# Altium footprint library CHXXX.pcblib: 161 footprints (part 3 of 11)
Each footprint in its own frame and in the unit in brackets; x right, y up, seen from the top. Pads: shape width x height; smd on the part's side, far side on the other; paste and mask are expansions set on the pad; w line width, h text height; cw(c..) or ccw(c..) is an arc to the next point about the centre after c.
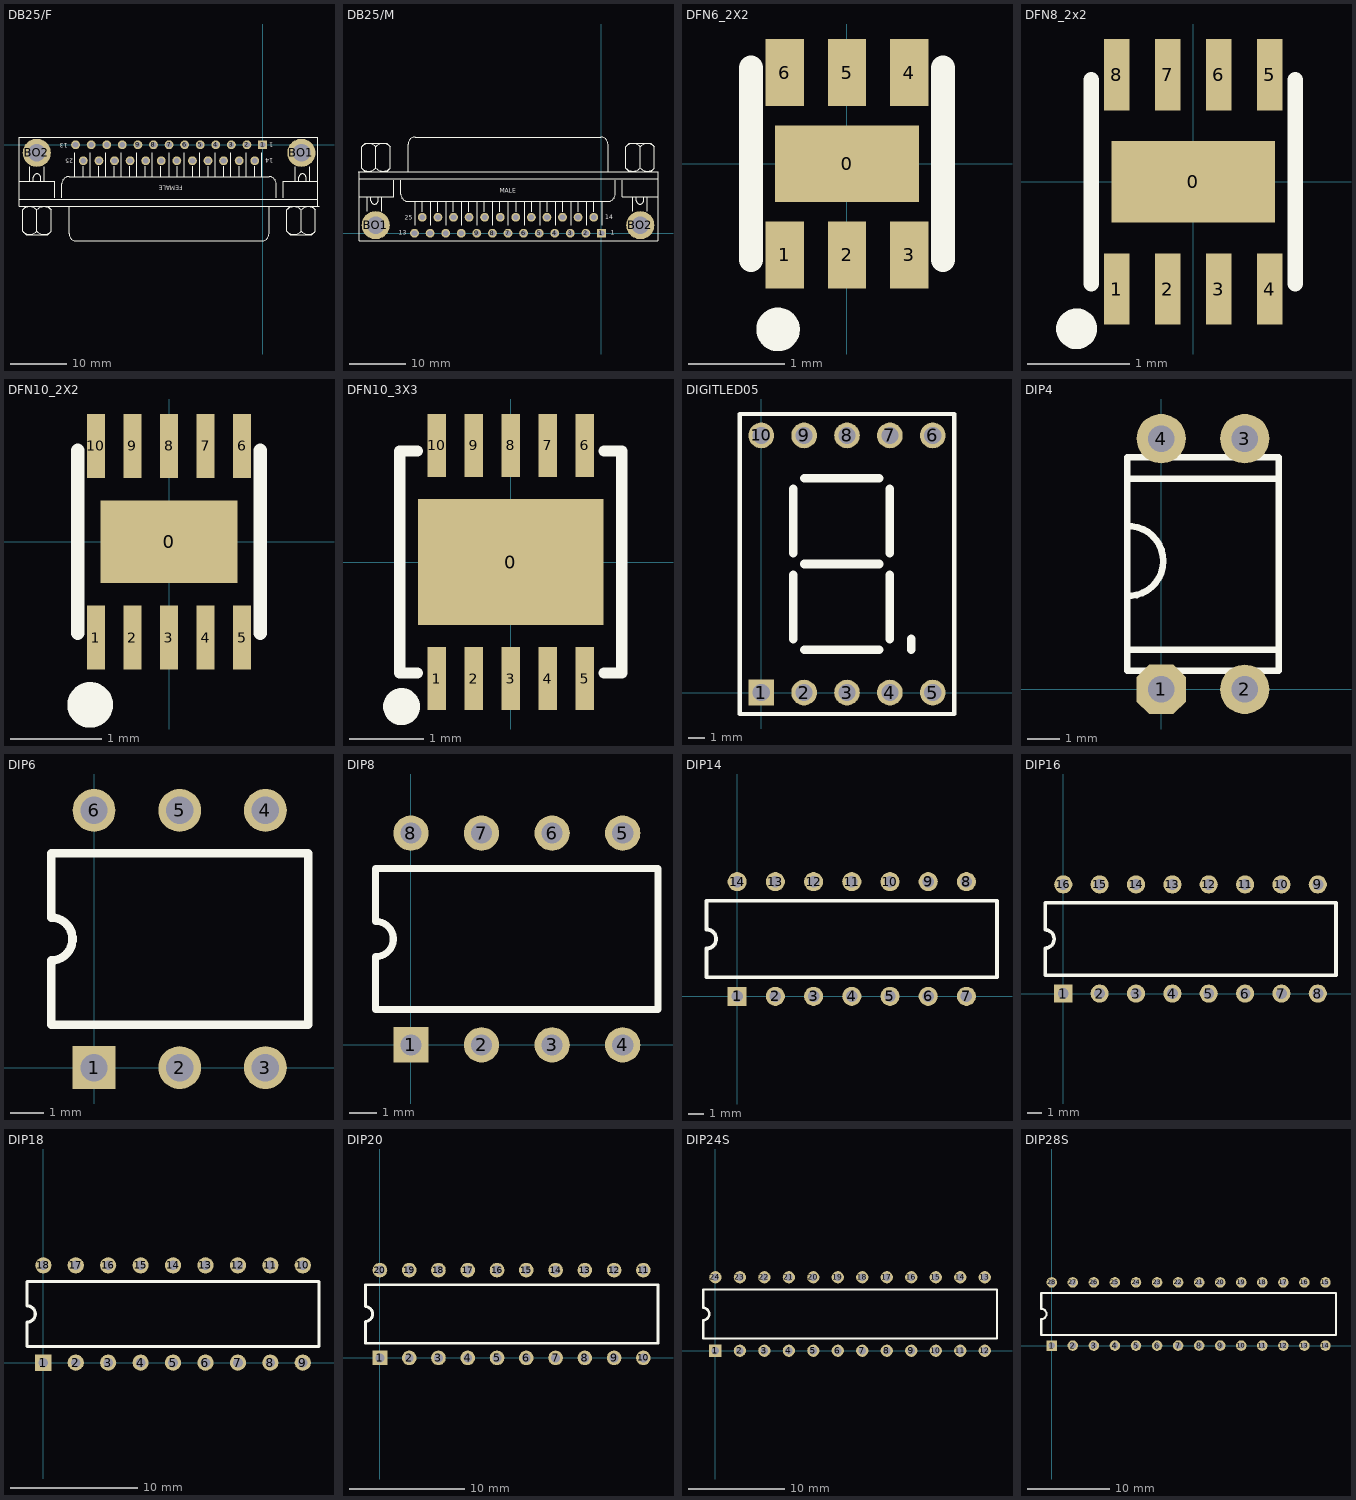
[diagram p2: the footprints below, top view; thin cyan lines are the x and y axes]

## DB25/F [mm]
pads (27):
  rect 1.575x1.575 hole 1.016: 1(0,0)
  round 1.575 hole 1.016: 2(-2.77,0) 3(-5.54,0) 4(-8.31,0) 5(-11.08,0) 6(-13.85,0) 7(-16.62,0) 8(-19.39,0) 9(-22.16,0) 10(-24.93,0) 11(-27.7,0) 12(-30.47,0) 13(-33.24,0) 14(-1.385,-2.84) 15(-4.155,-2.84) 16(-6.925,-2.84) 17(-9.695,-2.84) 18(-12.465,-2.84) 19(-15.235,-2.84) 20(-18.005,-2.84) 21(-20.775,-2.84) 22(-23.545,-2.84) 23(-26.315,-2.84) 24(-29.085,-2.84) 25(-31.855,-2.84)
  round 4.995 hole 3.18: BO1(6.9,-1.42) BO2(-40.14,-1.42)
TopOverlay:
  lines w0.203: -43.297,-6.436 -36.947,-6.436 -36.947,-9.455 ; -43.297,1.364 -43.297,-10.936 10.043,-10.936 ; -43.262,-9.636 9.838,-9.636 ; -43.262,1.364 9.838,1.364 9.838,-10.936 ; -42.665,-15.384 ccw(c-41.392,-14.111) -40.12,-15.384 ; -42.665,-11.569 cw(c-41.392,-12.841) -40.12,-11.569 ; -42.027,-10.936 -42.662,-11.571 -42.662,-15.381 -42.027,-16.016 -38.217,-16.016 -37.582,-15.381 -37.582,-11.571 -38.217,-10.936 ; -41.37,-6.436 -41.37,-3.896 ; -40.735,-6.436 -40.735,-5.801 cw(c-40.1,-5.801) -39.465,-5.801 -39.465,-6.436 ; -40.125,-15.384 ccw(c-38.852,-14.111) -37.58,-15.384 ; -40.125,-11.569 cw(c-38.852,-12.841) -37.58,-11.569 ; -40.122,-15.381 -40.122,-11.571 ; -38.83,-6.436 -38.83,-3.896 ; -35.677,-9.455 -35.677,-6.915 cw(c-34.407,-6.915) -34.407,-5.645 1.153,-5.645 cw(c1.153,-6.915) 2.423,-6.915 2.423,-9.455 ; -34.407,-10.936 -34.407,-15.805 ccw(c-33.137,-15.805) -33.137,-17.075 -32.502,-17.075 -0.117,-17.075 ccw(c-0.117,-15.805) 1.153,-15.805 1.153,-10.936 ; -33.349,-5.645 -33.349,-1.418 ; -31.867,-5.645 -31.867,-3.836 ; -30.597,-5.645 -30.597,-1.418 ; -29.116,-5.645 -29.116,-3.836 ; -27.846,-5.645 -27.846,-1.418 ; -26.364,-5.645 -26.364,-3.836 ; -25.094,-5.645 -25.094,-1.418 ; -23.612,-5.645 -23.612,-3.836 ; -22.342,-5.645 -22.342,-1.418 ; -20.861,-5.645 -20.861,-3.836 ; -19.591,-5.645 -19.591,-1.418 ; -18.109,-5.645 -18.109,-3.836 ; -16.627,-5.645 -16.627,-1.418 ; -15.146,-5.645 -15.146,-3.836 ; -13.876,-5.645 -13.876,-1.418 ; -12.394,-5.645 -12.394,-3.836 ; -11.124,-5.645 -11.124,-1.418 ; -9.642,-5.645 -9.642,-3.836 ; -8.372,-5.645 -8.372,-1.418 ; -6.891,-5.645 -6.891,-3.836 ; -5.621,-5.645 -5.621,-1.418 ; -4.139,-5.645 -4.139,-3.836 ; -2.869,-5.645 -2.869,-1.418 ; -1.387,-5.645 -1.387,-3.836 ; -0.117,-5.645 -0.117,-1.418 ; 3.693,-9.455 3.693,-6.436 9.838,-6.436 ; 4.325,-15.384 ccw(c5.598,-14.111) 6.87,-15.384 ; 4.325,-11.569 cw(c5.598,-12.841) 6.87,-11.569 ; 4.963,-10.936 4.328,-11.571 4.328,-15.381 4.963,-16.016 8.773,-16.016 9.408,-15.381 9.408,-11.571 8.773,-10.936 ; 5.83,-6.436 5.83,-3.896 ; 6.465,-6.436 6.465,-5.801 cw(c7.1,-5.801) 7.735,-5.801 7.735,-6.436 ; 6.865,-15.384 ccw(c8.138,-14.111) 9.41,-15.384 ; 6.865,-11.569 cw(c8.138,-12.841) 9.41,-11.569 ; 6.868,-15.381 6.868,-11.571 ; 8.37,-6.436 8.37,-3.896
  text "25" at -33.665,-2.445 h0.76
  text "13" at -34.59,0.283 h0.76
  text "1" at 1.865,0.395 h0.76
  text "14" at 1.87,-2.382 h0.76
  text "FEMALE" at -14.19,-7.256 h0.76

## DB25/M [mm]
pads (27):
  rect 1.575x1.575 hole 1.016: 1(0,0)
  round 1.575 hole 1.016: 2(-2.77,0) 3(-5.54,0) 4(-8.31,0) 5(-11.08,0) 6(-13.85,0) 7(-16.62,0) 8(-19.39,0) 9(-22.16,0) 10(-24.93,0) 11(-27.7,0) 12(-30.47,0) 13(-33.24,0) 14(-1.385,2.84) 15(-4.155,2.84) 16(-6.925,2.84) 17(-9.695,2.84) 18(-12.465,2.84) 19(-15.235,2.84) 20(-18.005,2.84) 21(-20.775,2.84) 22(-23.545,2.84) 23(-26.315,2.84) 24(-29.085,2.84) 25(-31.855,2.84)
  round 4.995 hole 3.18: BO1(-40.14,1.42) BO2(6.9,1.42)
TopOverlay:
  lines w0.203: -43.29,10.936 10.05,10.936 10.05,-1.364 ; -43.085,6.436 -36.94,6.436 -36.94,9.455 ; -43.085,9.636 10.015,9.636 ; -43.085,10.936 -43.085,-1.364 10.015,-1.364 ; -42.657,11.569 ccw(c-41.385,12.841) -40.113,11.569 ; -42.657,15.384 cw(c-41.385,14.111) -40.113,15.384 ; -42.02,10.936 -42.655,11.571 -42.655,15.381 -42.02,16.016 -38.21,16.016 -37.575,15.381 -37.575,11.571 -38.21,10.936 ; -41.618,3.896 -41.618,6.436 ; -40.983,6.436 -40.983,5.801 ccw(c-40.348,5.801) -39.713,5.801 -39.713,6.436 ; -40.117,11.569 ccw(c-38.845,12.841) -37.573,11.569 ; -40.117,15.384 cw(c-38.845,14.111) -37.573,15.384 ; -40.115,11.571 -40.115,15.381 ; -39.078,3.896 -39.078,6.436 ; -35.67,9.455 -35.67,6.915 ccw(c-34.4,6.915) -34.4,5.645 1.16,5.645 ccw(c1.16,6.915) 2.43,6.915 2.43,9.455 ; -34.4,10.936 -34.4,15.805 cw(c-33.13,15.805) -33.13,17.075 -0.745,17.075 -0.11,17.075 cw(c-0.11,15.805) 1.16,15.805 1.16,10.936 ; -33.13,1.418 -33.13,5.645 ; -31.86,3.836 -31.86,5.645 ; -30.378,1.418 -30.378,5.645 ; -29.108,3.836 -29.108,5.645 ; -27.627,1.418 -27.627,5.645 ; -26.357,3.836 -26.357,5.645 ; -24.875,1.418 -24.875,5.645 ; -23.605,3.836 -23.605,5.645 ; -22.123,1.418 -22.123,5.645 ; -20.853,3.836 -20.853,5.645 ; -19.372,1.418 -19.372,5.645 ; -18.102,3.836 -18.102,5.645 ; -16.62,1.418 -16.62,5.645 ; -15.138,3.836 -15.138,5.645 ; -13.657,1.418 -13.657,5.645 ; -12.387,3.836 -12.387,5.645 ; -10.905,1.418 -10.905,5.645 ; -9.635,3.836 -9.635,5.645 ; -8.153,1.418 -8.153,5.645 ; -6.883,3.836 -6.883,5.645 ; -5.402,1.418 -5.402,5.645 ; -4.132,3.836 -4.132,5.645 ; -2.65,1.418 -2.65,5.645 ; -1.38,3.836 -1.38,5.645 ; 0.102,1.418 0.102,5.645 ; 3.7,9.455 3.7,6.436 10.05,6.436 ; 4.333,11.569 ccw(c5.605,12.841) 6.877,11.569 ; 4.333,15.384 cw(c5.605,14.111) 6.877,15.384 ; 4.97,10.936 4.335,11.571 4.335,15.381 4.97,16.016 8.78,16.016 9.415,15.381 9.415,11.571 8.78,10.936 ; 5.582,3.896 5.582,6.436 ; 6.217,6.436 6.217,5.801 ccw(c6.852,5.801) 7.487,5.801 7.487,6.436 ; 6.873,11.569 ccw(c8.145,12.841) 9.417,11.569 ; 6.873,15.384 cw(c8.145,14.111) 9.417,15.384 ; 6.875,11.571 6.875,15.381 ; 8.122,3.896 8.122,6.436
  text "MALE" at -18.107,7.215 h0.76
  text "14" at 0.652,2.434 h0.76
  text "1" at 1.625,-0.317 h0.76
  text "13" at -36.002,-0.284 h0.76
  text "25" at -34.937,2.391 h0.76

## DFN6_2X2 [mm]
pads (7):
  rect 1.5x0.8 smd mask+0.051: 0(0,0)
  rect 0.4x0.7 smd mask+0.051: 1(-0.65,-0.95) 2(0,-0.95) 3(0.65,-0.95) 4(0.65,0.95) 5(0,0.95) 6(-0.65,0.95)
TopOverlay:
  circle w0.254: c-0.718,-1.725 r0.1
  lines w0.254: -1,-1 -1,1 ; 1,-1 1,1

## DFN8_2x2 [mm]
pads (9):
  rect 1.6x0.8 smd mask+0.05: 0(0,0)
  rect 0.25x0.7 smd mask+0.05: 1(-0.75,-1.05) 2(-0.25,-1.05) 3(0.25,-1.05) 4(0.75,-1.05) 5(0.75,1.05) 6(0.25,1.05) 7(-0.25,1.05) 8(-0.75,1.05)
TopOverlay:
  circle w0.2: c-1.144,-1.44 r0.1
  lines w0.152: -1,-1 -1,1 ; 1,-1 1,1

## DFN10_2X2 [mm]
pads (11):
  rect 1.5x0.9 smd mask+0.051: 0(0,0)
  rect 0.2x0.7 smd mask+0.051: 1(-0.8,-1.05) 2(-0.4,-1.05) 3(0,-1.05) 4(0.4,-1.05) 5(0.8,-1.05) 6(0.8,1.05) 7(0.4,1.05) 8(0,1.05) 9(-0.4,1.05) 10(-0.8,1.05)
TopOverlay:
  circle w0.3: c-0.864,-1.786 r0.1
  lines w0.152: -1,-1 -1,1 ; 1,-1 1,1

## DFN10_3X3 [mm]
pads (11):
  rect 2.5x1.7 smd mask+0.051: 0(0,0)
  rect 0.25x0.85 smd mask+0.051: 1(-1,-1.575) 2(-0.5,-1.575) 3(0,-1.575) 4(0.5,-1.575) 5(1,-1.575) 6(1,1.575) 7(0.5,1.575) 8(0,1.575) 9(-0.5,1.575) 10(-1,1.575)
TopOverlay:
  circle w0.3: c-1.474,-1.954 r0.1
  lines w0.152: -1.264,-1.5 -1.5,-1.5 -1.5,1.5 -1.264,1.5 ; 1.264,-1.5 1.5,-1.5 1.5,1.5 1.264,1.5

## DIGITLED05 [mil]
pads (10):
  rect 60x60 hole 40: 1(0,0)
  round 60 hole 40: 2(100,0) 3(200,0) 4(300,0) 5(400,0) 6(400,600) 7(300,600) 8(200,600) 9(100,600) 10(0,600)
TopOverlay:
  lines w10: -50,-50 450,-50 450,650 -50,650 -50,-50
  lines w20: 75,125 75,275 ; 75,325 75,475 ; 100,100 275,100 ; 100,300 275,300 ; 100,500 275,500 ; 300,125 300,275 ; 300,325 300,475 ; 350,100 350,125

## DIP4 [mm]
pads (4):
  oct 1.5x1.5 hole 0.8: 1(0,0)
  round 1.5 hole 0.8: 2(2.54,0) 3(2.54,7.62) 4(0,7.62)
TopOverlay:
  lines w0.2: -1,1.2 3.5,1.2 ; -1,6.4 3.57,6.4 ; -1.03,0.56 -1.03,7.06 3.57,7.06 3.57,0.56 -1.03,0.56
  lines w0.203: -0.912,2.841 ccw(c-1,3.9) -0.904,4.959

## DIP6 [mil]
pads (6):
  rect 50x50 hole 32: 1(0,0)
  round 50 hole 32: 2(100,0) 3(200,0) 4(200,300) 5(100,300) 6(0,300)
TopOverlay:
  lines w10: -50,50 250,50 250,250 -50,250 -50,175 cw(c-50,150) -50,125 -50,50

## DIP8 [mil]
pads (8):
  rect 50x50 hole 30: 1(0,0)
  round 50 hole 30: 2(100,0) 3(200,0) 4(300,0) 5(300,300) 6(200,300) 7(100,300) 8(0,300)
TopOverlay:
  lines w10: -50,50 -50,125 ccw(c-50,150) -50,175 -50,250 350,250 350,50 -50,50

## DIP14 [mil]
pads (14):
  rect 50x50 hole 30: 1(0,0)
  round 50 hole 30: 2(100,0) 3(200,0) 4(300,0) 5(400,0) 6(500,0) 7(600,0) 8(600,300) 9(500,300) 10(400,300) 11(300,300) 12(200,300) 13(100,300) 14(0,300)
TopOverlay:
  lines w10: -80,50 680,50 680,250 -80,250 -80,175 cw(c-80,150) -80,125 -80,50

## DIP16 [mil]
pads (16):
  rect 50x50 hole 30: 1(0,0)
  round 50 hole 30: 2(100,0) 3(200,0) 4(300,0) 5(400,0) 6(500,0) 7(600,0) 8(700,0) 9(700,300) 10(600,300) 11(500,300) 12(400,300) 13(300,300) 14(200,300) 15(100,300) 16(0,300)
TopOverlay:
  lines w10: -50,50 -50,125 ccw(c-50,150) -50,175 -50,250 750,250 750,50 -50,50

## DIP18 [mil]
pads (18):
  rect 50x50 hole 30: 1(0,0)
  round 50 hole 30: 2(100,0) 3(200,0) 4(300,0) 5(400,0) 6(500,0) 7(600,0) 8(700,0) 9(800,0) 10(800,300) 11(700,300) 12(600,300) 13(500,300) 14(400,300) 15(300,300) 16(200,300) 17(100,300) 18(0,300)
TopOverlay:
  lines w10: -50,50 850,50 850,250 -50,250 -50,175 cw(c-50,150) -50,125 -50,50

## DIP20 [mil]
pads (20):
  rect 50x50 hole 30: 1(0,0)
  round 50 hole 30: 2(100,0) 3(200,0) 4(300,0) 5(400,0) 6(500,0) 7(600,0) 8(700,0) 9(800,0) 10(900,0) 11(900,300) 12(800,300) 13(700,300) 14(600,300) 15(500,300) 16(400,300) 17(300,300) 18(200,300) 19(100,300) 20(0,300)
TopOverlay:
  lines w10: -50,50 950,50 950,250 -50,250 -50,175 cw(c-50,150) -50,125 -50,50

## DIP24S [mil]
pads (24):
  rect 50x50 hole 30: 1(0,0)
  round 50 hole 30: 2(100,0) 3(200,0) 4(300,0) 5(400,0) 6(500,0) 7(600,0) 8(700,0) 9(800,0) 10(900,0) 11(1000,0) 12(1100,0) 13(1100,300) 14(1000,300) 15(900,300) 16(800,300) 17(700,300) 18(600,300) 19(500,300) 20(400,300) 21(300,300) 22(200,300) 23(100,300) 24(0,300)
TopOverlay:
  lines w10: -50,50 1150,50 1150,250 -50,250 -50,175 cw(c-50,150) -50,125 -50,50

## DIP28S [mil]
pads (28):
  rect 50x50 hole 30: 1(0,0)
  round 50 hole 30: 2(100,0) 3(200,0) 4(300,0) 5(400,0) 6(500,0) 7(600,0) 8(700,0) 9(800,0) 10(900,0) 11(1000,0) 12(1100,0) 13(1200,0) 14(1300,0) 15(1300,300) 16(1200,300) 17(1100,300) 18(1000,300) 19(900,300) 20(800,300) 21(700,300) 22(600,300) 23(500,300) 24(400,300) 25(300,300) 26(200,300) 27(100,300) 28(0,300)
TopOverlay:
  lines w10: -50,50 1350,50 1350,250 -50,250 -50,175 cw(c-50,150) -50,125 -50,50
